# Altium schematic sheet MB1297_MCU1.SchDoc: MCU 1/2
size A4; Date: Not used; ApprovedBy: Not used; CheckedBy: Not used; Author: Not used; CompanyName: STMicroelectronics; DrawnBy: Not used; Engineer: Not used; Organization: Not used; Address1: Not used; Address2: Not used; Address3: Not used; Address4: Not used; DocumentNumber: Not used; Revision: Not used; SheetNumber: 3; SheetTotal: 12
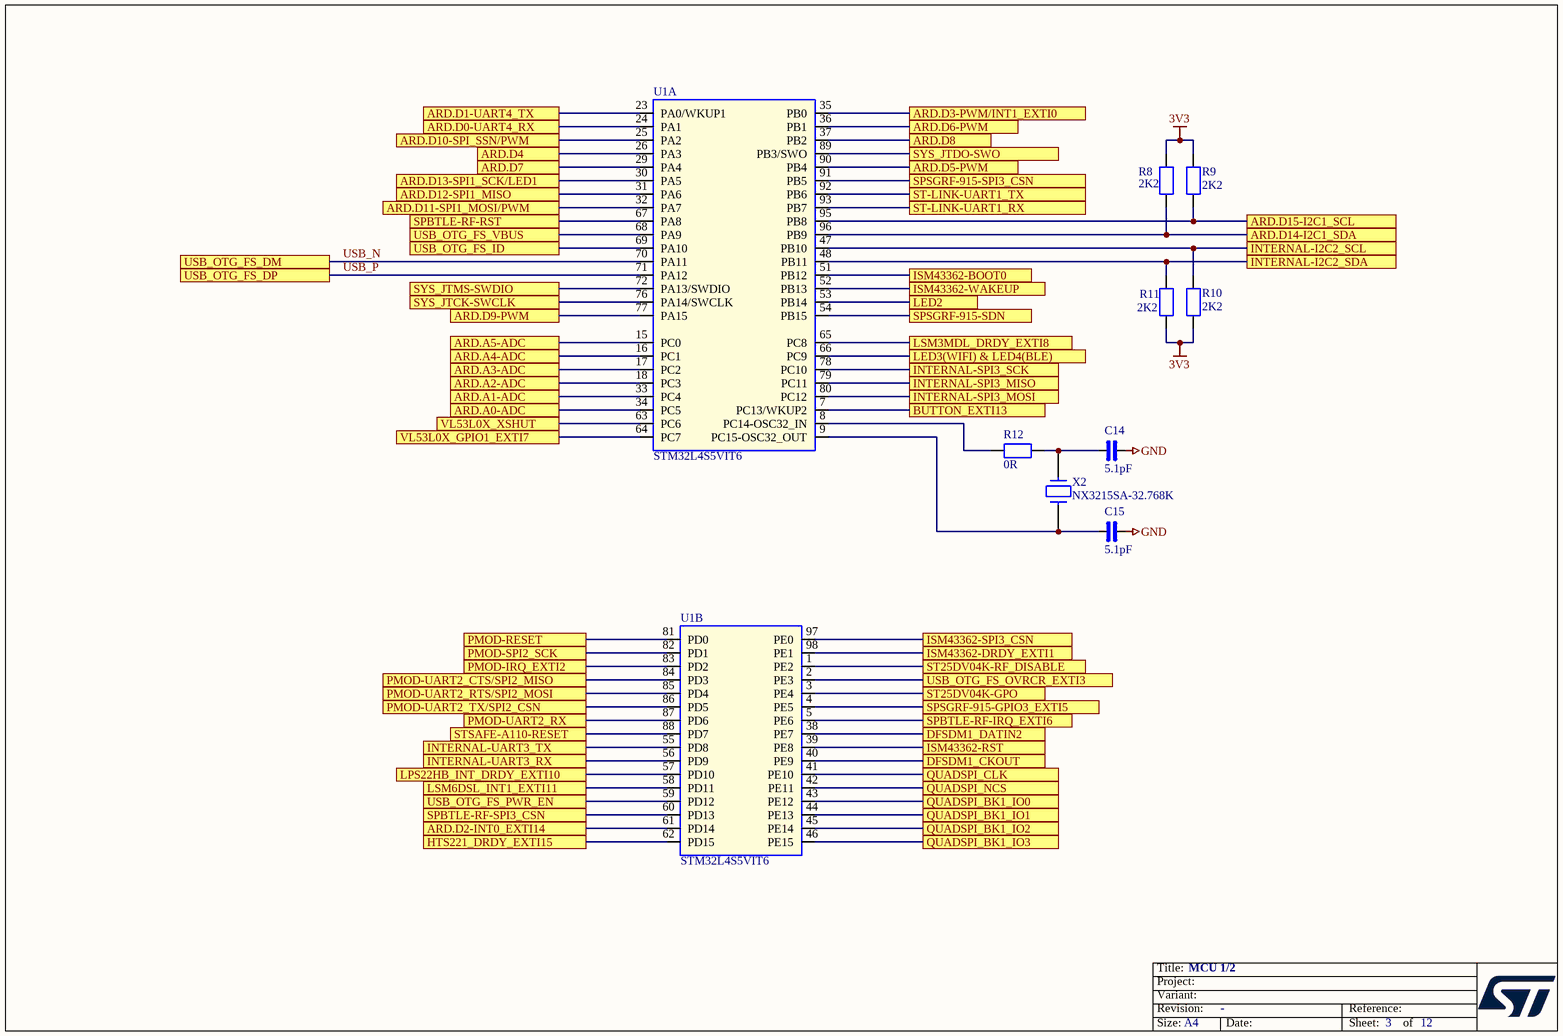
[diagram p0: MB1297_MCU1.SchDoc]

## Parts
C14  5.1pF  [0402]
C15  5.1pF  [0402]
R8  2K2  [0402]
R9  2K2  [0402]
R10  2K2  [0402]
R11  2K2  [0402]
R12  0R  [0402]
U1  STM32L4S5VIT6  [LQFP100 14x14x1.6]  (parts A,B of 3)
X2  NX3215SA-32.768K  [CRY_NX3215SA_2P]

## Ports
ARD.A0-ADC, ARD.A1-ADC, ARD.A2-ADC, ARD.A3-ADC, ARD.A4-ADC, ARD.A5-ADC, ARD.D0-UART4_RX, ARD.D1-UART4_TX, ARD.D2-INT0_EXTI14, ARD.D3-PWM/INT1_EXTI0, ARD.D4, ARD.D5-PWM, ARD.D6-PWM, ARD.D7, ARD.D8, ARD.D9-PWM, ARD.D10-SPI_SSN/PWM, ARD.D11-SPI1_MOSI/PWM, ARD.D12-SPI1_MISO, ARD.D13-SPI1_SCK/LED1, ARD.D14-I2C1_SDA, ARD.D15-I2C1_SCL, BUTTON_EXTI13, DFSDM1_CKOUT, DFSDM1_DATIN2, HTS221_DRDY_EXTI15, INTERNAL-I2C2_SCL, INTERNAL-I2C2_SDA, INTERNAL-SPI3_MISO, INTERNAL-SPI3_MOSI, INTERNAL-SPI3_SCK, INTERNAL-UART3_RX, INTERNAL-UART3_TX, ISM43362-BOOT0, ISM43362-DRDY_EXTI1, ISM43362-RST, ISM43362-SPI3_CSN, ISM43362-WAKEUP, LED2, LED3(WIFI) & LED4(BLE), LPS22HB_INT_DRDY_EXTI10, LSM3MDL_DRDY_EXTI8, LSM6DSL_INT1_EXTI11, PMOD-IRQ_EXTI2, PMOD-RESET, PMOD-SPI2_SCK, PMOD-UART2_CTS/SPI2_MISO, PMOD-UART2_RTS/SPI2_MOSI, PMOD-UART2_RX, PMOD-UART2_TX/SPI2_CSN, QUADSPI_BK1_IO0, QUADSPI_BK1_IO1, QUADSPI_BK1_IO2, QUADSPI_BK1_IO3, QUADSPI_CLK, QUADSPI_NCS, SPBTLE-RF-IRQ_EXTI6, SPBTLE-RF-RST, SPBTLE-RF-SPI3_CSN, SPSGRF-915-GPIO3_EXTI5, SPSGRF-915-SDN, SPSGRF-915-SPI3_CSN, ST25DV04K-GPO, ST25DV04K-RF_DISABLE, ST-LINK-UART1_RX, ST-LINK-UART1_TX, STSAFE-A110-RESET, SYS_JTCK-SWCLK, SYS_JTDO-SWO, SYS_JTMS-SWDIO, USB_OTG_FS_DM, USB_OTG_FS_DP, USB_OTG_FS_ID, USB_OTG_FS_OVRCR_EXTI3, USB_OTG_FS_PWR_EN, USB_OTG_FS_VBUS, VL53L0X_GPIO1_EXTI7, VL53L0X_XSHUT

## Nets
3V3: R8.1 R9.1 R10.1 R11.1
GND: C14.2 C15.2
ARD.A0-ADC: U1.34(PC5) ; port ARD.A0-ADC
ARD.A1-ADC: U1.33(PC4) ; port ARD.A1-ADC
ARD.A2-ADC: U1.18(PC3) ; port ARD.A2-ADC
ARD.A3-ADC: U1.17(PC2) ; port ARD.A3-ADC
ARD.A4-ADC: U1.16(PC1) ; port ARD.A4-ADC
ARD.A5-ADC: U1.15(PC0) ; port ARD.A5-ADC
ARD.D0-UART4_RX: U1.24(PA1) ; port ARD.D0-UART4_RX
ARD.D1-UART4_TX: U1.23(PA0/WKUP1) ; port ARD.D1-UART4_TX
ARD.D2-INT0_EXTI14: U1.61(PD14) ; port ARD.D2-INT0_EXTI14
ARD.D3-PWM/INT1_EXTI0: U1.35(PB0) ; port ARD.D3-PWM/INT1_EXTI0
ARD.D4: U1.26(PA3) ; port ARD.D4
ARD.D5-PWM: U1.90(PB4) ; port ARD.D5-PWM
ARD.D6-PWM: U1.36(PB1) ; port ARD.D6-PWM
ARD.D7: U1.29(PA4) ; port ARD.D7
ARD.D8: U1.37(PB2) ; port ARD.D8
ARD.D9-PWM: U1.77(PA15) ; port ARD.D9-PWM
ARD.D10-SPI_SSN/PWM: U1.25(PA2) ; port ARD.D10-SPI_SSN/PWM
ARD.D11-SPI1_MOSI/PWM: U1.32(PA7) ; port ARD.D11-SPI1_MOSI/PWM
ARD.D12-SPI1_MISO: U1.31(PA6) ; port ARD.D12-SPI1_MISO
ARD.D13-SPI1_SCK/LED1: U1.30(PA5) ; port ARD.D13-SPI1_SCK/LED1
ARD.D14-I2C1_SDA: R8.2 U1.96(PB9) ; port ARD.D14-I2C1_SDA
ARD.D15-I2C1_SCL: R9.2 U1.95(PB8) ; port ARD.D15-I2C1_SCL
BUTTON_EXTI13: U1.7(PC13/WKUP2) ; port BUTTON_EXTI13
DFSDM1_CKOUT: U1.40(PE9) ; port DFSDM1_CKOUT
DFSDM1_DATIN2: U1.38(PE7) ; port DFSDM1_DATIN2
HTS221_DRDY_EXTI15: U1.62(PD15) ; port HTS221_DRDY_EXTI15
INTERNAL-I2C2_SCL: R10.2 U1.47(PB10) ; port INTERNAL-I2C2_SCL
INTERNAL-I2C2_SDA: R11.2 U1.48(PB11) ; port INTERNAL-I2C2_SDA
INTERNAL-SPI3_MISO: U1.79(PC11) ; port INTERNAL-SPI3_MISO
INTERNAL-SPI3_MOSI: U1.80(PC12) ; port INTERNAL-SPI3_MOSI
INTERNAL-SPI3_SCK: U1.78(PC10) ; port INTERNAL-SPI3_SCK
INTERNAL-UART3_RX: U1.56(PD9) ; port INTERNAL-UART3_RX
INTERNAL-UART3_TX: U1.55(PD8) ; port INTERNAL-UART3_TX
ISM43362-BOOT0: U1.51(PB12) ; port ISM43362-BOOT0
ISM43362-DRDY_EXTI1: U1.98(PE1) ; port ISM43362-DRDY_EXTI1
ISM43362-RST: U1.39(PE8) ; port ISM43362-RST
ISM43362-SPI3_CSN: U1.97(PE0) ; port ISM43362-SPI3_CSN
ISM43362-WAKEUP: U1.52(PB13) ; port ISM43362-WAKEUP
LED2: U1.53(PB14) ; port LED2
LED3(WIFI) & LED4(BLE): U1.66(PC9) ; port LED3(WIFI) & LED4(BLE)
LPS22HB_INT_DRDY_EXTI10: U1.57(PD10) ; port LPS22HB_INT_DRDY_EXTI10
LSM3MDL_DRDY_EXTI8: U1.65(PC8) ; port LSM3MDL_DRDY_EXTI8
LSM6DSL_INT1_EXTI11: U1.58(PD11) ; port LSM6DSL_INT1_EXTI11
PMOD-IRQ_EXTI2: U1.83(PD2) ; port PMOD-IRQ_EXTI2
PMOD-RESET: U1.81(PD0) ; port PMOD-RESET
PMOD-SPI2_SCK: U1.82(PD1) ; port PMOD-SPI2_SCK
PMOD-UART2_CTS/SPI2_MISO: U1.84(PD3) ; port PMOD-UART2_CTS/SPI2_MISO
PMOD-UART2_RTS/SPI2_MOSI: U1.85(PD4) ; port PMOD-UART2_RTS/SPI2_MOSI
PMOD-UART2_RX: U1.87(PD6) ; port PMOD-UART2_RX
PMOD-UART2_TX/SPI2_CSN: U1.86(PD5) ; port PMOD-UART2_TX/SPI2_CSN
QUADSPI_BK1_IO0: U1.43(PE12) ; port QUADSPI_BK1_IO0
QUADSPI_BK1_IO1: U1.44(PE13) ; port QUADSPI_BK1_IO1
QUADSPI_BK1_IO2: U1.45(PE14) ; port QUADSPI_BK1_IO2
QUADSPI_BK1_IO3: U1.46(PE15) ; port QUADSPI_BK1_IO3
QUADSPI_CLK: U1.41(PE10) ; port QUADSPI_CLK
QUADSPI_NCS: U1.42(PE11) ; port QUADSPI_NCS
SPBTLE-RF-IRQ_EXTI6: U1.5(PE6) ; port SPBTLE-RF-IRQ_EXTI6
SPBTLE-RF-RST: U1.67(PA8) ; port SPBTLE-RF-RST
SPBTLE-RF-SPI3_CSN: U1.60(PD13) ; port SPBTLE-RF-SPI3_CSN
SPSGRF-915-GPIO3_EXTI5: U1.4(PE5) ; port SPSGRF-915-GPIO3_EXTI5
SPSGRF-915-SDN: U1.54(PB15) ; port SPSGRF-915-SDN
SPSGRF-915-SPI3_CSN: U1.91(PB5) ; port SPSGRF-915-SPI3_CSN
ST25DV04K-GPO: U1.3(PE4) ; port ST25DV04K-GPO
ST25DV04K-RF_DISABLE: U1.1(PE2) ; port ST25DV04K-RF_DISABLE
ST-LINK-UART1_RX: U1.93(PB7) ; port ST-LINK-UART1_RX
ST-LINK-UART1_TX: U1.92(PB6) ; port ST-LINK-UART1_TX
STSAFE-A110-RESET: U1.88(PD7) ; port STSAFE-A110-RESET
SYS_JTCK-SWCLK: U1.76(PA14/SWCLK) ; port SYS_JTCK-SWCLK
SYS_JTDO-SWO: U1.89(PB3/SWO) ; port SYS_JTDO-SWO
SYS_JTMS-SWDIO: U1.72(PA13/SWDIO) ; port SYS_JTMS-SWDIO
USB_N: U1.70(PA11) ; port USB_OTG_FS_DM
USB_OTG_FS_ID: U1.69(PA10) ; port USB_OTG_FS_ID
USB_OTG_FS_OVRCR_EXTI3: U1.2(PE3) ; port USB_OTG_FS_OVRCR_EXTI3
USB_OTG_FS_PWR_EN: U1.59(PD12) ; port USB_OTG_FS_PWR_EN
USB_OTG_FS_VBUS: U1.68(PA9) ; port USB_OTG_FS_VBUS
USB_P: U1.71(PA12) ; port USB_OTG_FS_DP
VL53L0X_GPIO1_EXTI7: U1.64(PC7) ; port VL53L0X_GPIO1_EXTI7
VL53L0X_XSHUT: U1.63(PC6) ; port VL53L0X_XSHUT
NetC14_1: C14.1 R12.2 X2.1
NetC15_1: C15.1 U1.9(PC15-OSC32_OUT) X2.2
NetR12_1: R12.1 U1.8(PC14-OSC32_IN)

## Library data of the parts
C14 C15 = CAP_NPOL: Capacitor_not polarized
R8-R12 = RES: Resistor
U1 = STM32L475VGTx
X2 = XTAL_32K_NX3215SA: Crystal 32.768kHz, 6pF, -+20PPM, R=50K, SMD; Manuf_1: NDK; Manuf_Part_1: NX3215SA 32.768KHz EXS00A-MU00525; ECCN_US/EU: EAR99/NEC; Ref St: 9157034; NDK Ref: X3101802; Fitted: YES; Ordered_By: STM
